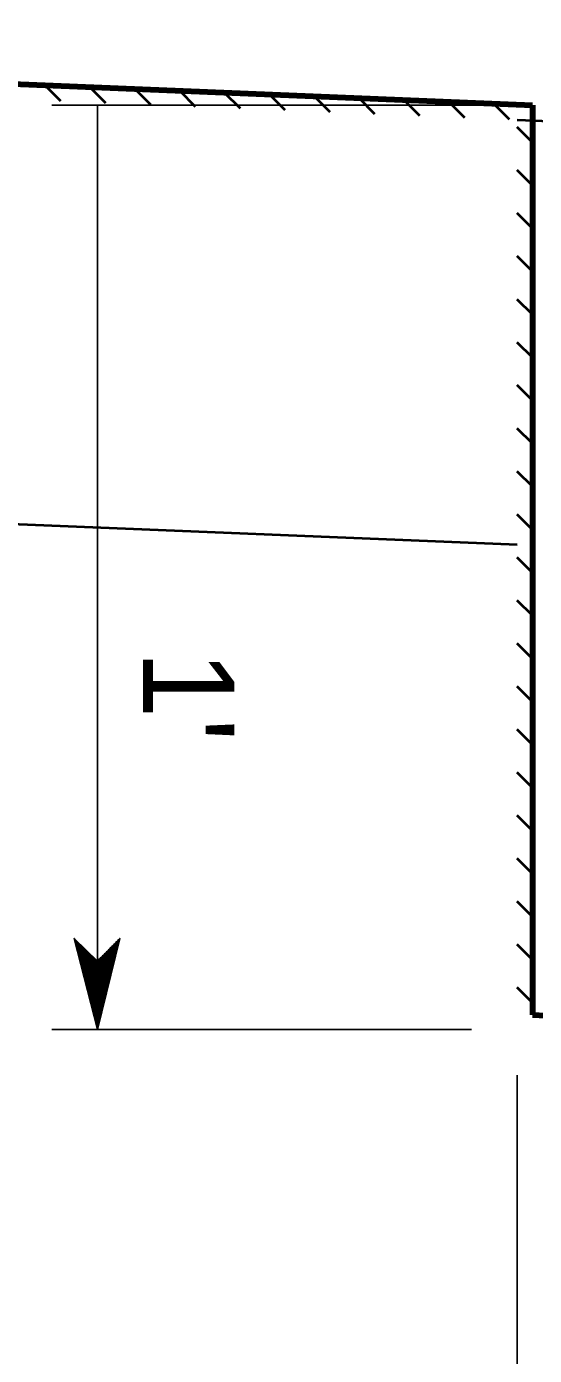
# Model space of a CAD drawing. Extents: x -48732 to -48696.6, y -117659.8 to -117637.8.
# Drawn here: x -48725.971 to -48725.536, y -117657.175 to -117656.038 of the extents above; entities that cross this region are included whole.
import ezdxf

# ---------------------------------------------------------------- set-up
doc = ezdxf.new("R2010")
doc.units = 0
doc.header["$LTSCALE"] = 0.048
doc.linetypes.add('DOTTED', pattern=[1.5, 0.3, -1.2])
doc.layers.add('11', color=7, linetype='Continuous', lineweight=25)
doc.layers.add('24', color=7, linetype='Continuous', lineweight=40)

msp = doc.modelspace()

# ---------------------------------------------------------------- linework, layer by layer
at = {"layer": '11'}
for p, q in [((-48725.57708, -117656.10492), (-48725.94942, -117656.10492)), ((-48725.91042, -117656.89617), (-48725.91042, -117656.10492)), ((-48725.92992, -117656.81833), (-48725.93008, -117656.81842)), ((-48725.92958, -117656.81858), (-48725.93, -117656.81892)), ((-48725.92925, -117656.81892), (-48725.92992, -117656.81942)), ((-48725.92892, -117656.81925), (-48725.92975, -117656.81983)), ((-48725.92858, -117656.81958), (-48725.92958, -117656.82025)), ((-48725.92825, -117656.81992), (-48725.92958, -117656.82075)), ((-48725.928, -117656.82025), (-48725.92942, -117656.82125)), ((-48725.92767, -117656.82058), (-48725.92925, -117656.82167)), ((-48725.92742, -117656.82092), (-48725.92925, -117656.82208)), ((-48725.92708, -117656.82125), (-48725.92908, -117656.82258)), ((-48725.92675, -117656.8215), (-48725.92892, -117656.82308)), ((-48725.92642, -117656.82175), (-48725.92883, -117656.8235)), ((-48725.92608, -117656.82208), (-48725.92875, -117656.82392)), ((-48725.92575, -117656.82242), (-48725.92858, -117656.82442)), ((-48725.92542, -117656.82275), (-48725.92842, -117656.82492)), ((-48725.92508, -117656.82308), (-48725.92842, -117656.82533)), ((-48725.92475, -117656.82342), (-48725.92825, -117656.82575)), ((-48725.92442, -117656.82375), (-48725.92808, -117656.82625)), ((-48725.92408, -117656.82408), (-48725.92808, -117656.82675)), ((-48725.92375, -117656.82442), (-48725.92792, -117656.82708)), ((-48725.9235, -117656.82467), (-48725.92775, -117656.82758)), ((-48725.92317, -117656.825), (-48725.92767, -117656.82808)), ((-48725.92292, -117656.82525), (-48725.92758, -117656.82858)), ((-48725.92258, -117656.82558), (-48725.92742, -117656.82892)), ((-48725.89292, -117656.82525), (-48725.90958, -117656.83658)), ((-48725.89275, -117656.82458), (-48725.90792, -117656.83492)), ((-48725.89258, -117656.82392), (-48725.90625, -117656.83325)), ((-48725.89242, -117656.82325), (-48725.90458, -117656.83158)), ((-48725.89225, -117656.82267), (-48725.90292, -117656.82992)), ((-48725.89208, -117656.822), (-48725.90125, -117656.82825)), ((-48725.89192, -117656.82142), (-48725.89967, -117656.82658)), ((-48725.89175, -117656.82075), (-48725.89808, -117656.82492)), ((-48725.89167, -117656.82008), (-48725.89642, -117656.82325)), ((-48725.8915, -117656.81942), (-48725.89475, -117656.82158)), ((-48725.89142, -117656.81875), (-48725.89308, -117656.81992)), ((-48725.89125, -117656.81808), (-48725.89142, -117656.81825)), ((-48725.92225, -117656.82592), (-48725.92725, -117656.82942)), ((-48725.92192, -117656.82625), (-48725.92725, -117656.82992)), ((-48725.92158, -117656.82658), (-48725.92708, -117656.83042)), ((-48725.92125, -117656.82692), (-48725.92692, -117656.83075)), ((-48725.92092, -117656.82725), (-48725.92692, -117656.83125)), ((-48725.92058, -117656.82758), (-48725.92675, -117656.83175)), ((-48725.92025, -117656.82792), (-48725.92658, -117656.83225)), ((-48725.91992, -117656.82817), (-48725.9265, -117656.83258)), ((-48725.91958, -117656.82842), (-48725.92642, -117656.83308)), ((-48725.91925, -117656.82875), (-48725.92625, -117656.83358)), ((-48725.919, -117656.82908), (-48725.92617, -117656.83408)), ((-48725.91867, -117656.82942), (-48725.92608, -117656.83442)), ((-48725.91842, -117656.82975), (-48725.92592, -117656.83492)), ((-48725.91808, -117656.83008), (-48725.92575, -117656.83542)), ((-48725.91775, -117656.83042), (-48725.92575, -117656.83583)), ((-48725.91742, -117656.83075), (-48725.92558, -117656.83625)), ((-48725.91708, -117656.83108), (-48725.92542, -117656.83675)), ((-48725.91675, -117656.83133), (-48725.92533, -117656.83725)), ((-48725.91642, -117656.83158), (-48725.92525, -117656.83767)), ((-48725.91608, -117656.83192), (-48725.92508, -117656.83808)), ((-48725.91575, -117656.83225), (-48725.925, -117656.83858)), ((-48725.91542, -117656.83258), (-48725.92492, -117656.83908)), ((-48725.91508, -117656.83292), (-48725.92475, -117656.8395)), ((-48725.91483, -117656.83325), (-48725.92458, -117656.83992)), ((-48725.9145, -117656.83358), (-48725.92458, -117656.84042)), ((-48725.91425, -117656.83392), (-48725.92442, -117656.84092)), ((-48725.91392, -117656.83425), (-48725.92425, -117656.84133)), ((-48725.91358, -117656.8345), (-48725.92425, -117656.84175)), ((-48725.91325, -117656.83483), (-48725.92408, -117656.84225)), ((-48725.91292, -117656.83508), (-48725.92392, -117656.84275)), ((-48725.91258, -117656.83542), (-48725.92383, -117656.84317)), ((-48725.91225, -117656.83575), (-48725.92375, -117656.84358)), ((-48725.91192, -117656.83608), (-48725.92358, -117656.84408)), ((-48725.91158, -117656.83642), (-48725.92342, -117656.84458)), ((-48725.91125, -117656.83675), (-48725.92342, -117656.845)), ((-48725.91092, -117656.83708), (-48725.92325, -117656.84542)), ((-48725.89308, -117656.82592), (-48725.92308, -117656.84642)), ((-48725.89325, -117656.82658), (-48725.92292, -117656.84675)), ((-48725.89342, -117656.82717), (-48725.92275, -117656.84725)), ((-48725.89358, -117656.82783), (-48725.92267, -117656.84775)), ((-48725.89375, -117656.82842), (-48725.92258, -117656.84825)), ((-48725.89392, -117656.82908), (-48725.92242, -117656.84858)), ((-48725.89408, -117656.82975), (-48725.92225, -117656.84908)), ((-48725.89425, -117656.83042), (-48725.92225, -117656.84958)), ((-48725.89442, -117656.83108), (-48725.92208, -117656.85008)), ((-48725.89458, -117656.83175), (-48725.92192, -117656.85042)), ((-48725.89467, -117656.83233), (-48725.92192, -117656.85092)), ((-48725.89483, -117656.83292), (-48725.92175, -117656.85142)), ((-48725.895, -117656.83358), (-48725.92158, -117656.85192)), ((-48725.89508, -117656.83425), (-48725.9215, -117656.85225)), ((-48725.89525, -117656.83492), (-48725.92142, -117656.85275)), ((-48725.89542, -117656.83558), (-48725.92125, -117656.85325)), ((-48725.89558, -117656.83625), (-48725.92117, -117656.85367)), ((-48725.89575, -117656.83692), (-48725.92108, -117656.85408)), ((-48725.91058, -117656.83742), (-48725.92308, -117656.84592)), ((-48725.89592, -117656.8375), (-48725.92092, -117656.85458)), ((-48725.89608, -117656.83808), (-48725.92075, -117656.85508)), ((-48725.89625, -117656.83875), (-48725.92075, -117656.8555)), ((-48725.89642, -117656.83942), (-48725.92058, -117656.85592)), ((-48725.89658, -117656.84008), (-48725.92042, -117656.85642)), ((-48725.89675, -117656.84075), (-48725.92033, -117656.85692)), ((-48725.89692, -117656.84142), (-48725.92025, -117656.85733)), ((-48725.89708, -117656.84208), (-48725.92008, -117656.85775)), ((-48725.89725, -117656.84267), (-48725.92, -117656.85825)), ((-48725.89742, -117656.84325), (-48725.91992, -117656.85875)), ((-48725.89758, -117656.84392), (-48725.91975, -117656.85917)), ((-48725.89775, -117656.84458), (-48725.91958, -117656.85958)), ((-48725.89792, -117656.84525), (-48725.91958, -117656.86008)), ((-48725.898, -117656.84592), (-48725.91942, -117656.86058)), ((-48725.89817, -117656.84658), (-48725.91925, -117656.861)), ((-48725.89825, -117656.84725), (-48725.91925, -117656.86142)), ((-48725.89842, -117656.84783), (-48725.91908, -117656.86192)), ((-48725.89858, -117656.84842), (-48725.91892, -117656.86242)), ((-48725.89875, -117656.84908), (-48725.91883, -117656.86283)), ((-48725.89892, -117656.84975), (-48725.91875, -117656.86325)), ((-48725.89908, -117656.85042), (-48725.91858, -117656.86375)), ((-48725.89925, -117656.85108), (-48725.91842, -117656.86425)), ((-48725.89942, -117656.85175), (-48725.91842, -117656.86458)), ((-48725.89958, -117656.85233), (-48725.91825, -117656.86508)), ((-48725.89975, -117656.853), (-48725.91808, -117656.86558)), ((-48725.89992, -117656.85358), (-48725.91808, -117656.86608)), ((-48725.90008, -117656.85425), (-48725.91792, -117656.86642)), ((-48725.90025, -117656.85492), (-48725.91775, -117656.86692)), ((-48725.90042, -117656.85558), (-48725.91767, -117656.86742)), ((-48725.90058, -117656.85625), (-48725.91758, -117656.86792)), ((-48725.90075, -117656.85692), (-48725.91742, -117656.86825)), ((-48725.90092, -117656.8575), (-48725.91725, -117656.86875)), ((-48725.90108, -117656.85808), (-48725.91725, -117656.86925)), ((-48725.90117, -117656.85875), (-48725.91708, -117656.86975)), ((-48725.90133, -117656.85942), (-48725.91692, -117656.87008)), ((-48725.9015, -117656.86008), (-48725.91692, -117656.87058)), ((-48725.90158, -117656.86075), (-48725.91675, -117656.87108)), ((-48725.90175, -117656.86142), (-48725.91658, -117656.8715)), ((-48725.90192, -117656.86208), (-48725.9165, -117656.87192)), ((-48725.90208, -117656.86267), (-48725.91642, -117656.87242)), ((-48725.90225, -117656.86325), (-48725.91625, -117656.87292)), ((-48725.90242, -117656.86392), (-48725.91617, -117656.87333)), ((-48725.90258, -117656.86458), (-48725.91608, -117656.87375)), ((-48725.90275, -117656.86525), (-48725.91592, -117656.87425)), ((-48725.90292, -117656.86592), (-48725.91575, -117656.87475)), ((-48725.90308, -117656.86658), (-48725.91575, -117656.87517)), ((-48725.90325, -117656.86725), (-48725.91558, -117656.87558)), ((-48725.90342, -117656.86783), (-48725.91542, -117656.87608)), ((-48725.90358, -117656.86842), (-48725.91533, -117656.87658)), ((-48725.90375, -117656.86908), (-48725.91525, -117656.877)), ((-48725.90392, -117656.86975), (-48725.91508, -117656.87742)), ((-48725.90408, -117656.87042), (-48725.915, -117656.87792)), ((-48725.90425, -117656.87108), (-48725.91492, -117656.87842)), ((-48725.90442, -117656.87175), (-48725.91475, -117656.87883)), ((-48725.9045, -117656.87242), (-48725.91458, -117656.87925)), ((-48725.90467, -117656.873), (-48725.91458, -117656.87975)), ((-48725.90483, -117656.87358), (-48725.91442, -117656.88025)), ((-48725.90492, -117656.87425), (-48725.91425, -117656.88067)), ((-48725.90508, -117656.87492), (-48725.91425, -117656.88108)), ((-48725.90525, -117656.87558), (-48725.91408, -117656.88158)), ((-48725.90542, -117656.87625), (-48725.91392, -117656.88208)), ((-48725.90558, -117656.87692), (-48725.91383, -117656.8825)), ((-48725.90575, -117656.87758), (-48725.91375, -117656.88292)), ((-48725.90592, -117656.87817), (-48725.91358, -117656.88342)), ((-48725.90608, -117656.87875), (-48725.91342, -117656.88392)), ((-48725.90625, -117656.87942), (-48725.91342, -117656.88425)), ((-48725.90642, -117656.88008), (-48725.91325, -117656.88475)), ((-48725.90658, -117656.88075), (-48725.91308, -117656.88525)), ((-48725.90675, -117656.88142), (-48725.91308, -117656.88575)), ((-48725.90692, -117656.88208), (-48725.91292, -117656.88608)), ((-48725.90708, -117656.88267), (-48725.91275, -117656.88658)), ((-48725.90725, -117656.88333), (-48725.91267, -117656.88708)), ((-48725.90742, -117656.88392), (-48725.91258, -117656.88758)), ((-48725.90758, -117656.88458), (-48725.91242, -117656.88792)), ((-48725.90775, -117656.88525), (-48725.91225, -117656.88842)), ((-48725.90783, -117656.88592), (-48725.91225, -117656.88892)), ((-48725.908, -117656.88658), (-48725.91208, -117656.88942)), ((-48725.90808, -117656.88725), (-48725.91192, -117656.88975)), ((-48725.90825, -117656.88783), (-48725.91192, -117656.89025)), ((-48725.90842, -117656.88842), (-48725.91175, -117656.89075)), ((-48725.90858, -117656.88908), (-48725.91158, -117656.89117)), ((-48725.90875, -117656.88975), (-48725.9115, -117656.89158)), ((-48725.90892, -117656.89042), (-48725.91142, -117656.89208)), ((-48725.90908, -117656.89108), (-48725.91125, -117656.89258)), ((-48725.90925, -117656.89175), (-48725.91117, -117656.893)), ((-48725.90942, -117656.89242), (-48725.91108, -117656.89342)), ((-48725.90958, -117656.893), (-48725.91092, -117656.89392)), ((-48725.90975, -117656.89358), (-48725.91075, -117656.89442)), ((-48725.59008, -117656.89617), (-48725.94942, -117656.89617)), ((-48725.90992, -117656.89425), (-48725.91075, -117656.89483)), ((-48725.91008, -117656.89492), (-48725.91058, -117656.89525)), ((-48725.91025, -117656.89558), (-48725.91042, -117656.89575)), ((-48725.551, -117656.93525), (-48725.551, -117657.77692))]:
    msp.add_line(p, q, dxfattribs=at)
msp.add_lwpolyline([(-48725.91042, -117656.89617), (-48725.89117, -117656.81808), (-48725.91042, -117656.83758), (-48725.93025, -117656.81808)], close=True, dxfattribs=at)
at = {"layer": '24', "lineweight": 106}
for p, q in [((-48727.18058, -117656.03758), (-48725.53792, -117656.10492)), ((-48725.53792, -117656.10492), (-48725.53792, -117656.88367)), ((-48725.53792, -117656.88367), (-48724.97125, -117656.90875))]:
    msp.add_line(p, q, dxfattribs=at)
at = {"layer": '24'}
for p, q in [((-48725.94158, -117656.10142), (-48725.95508, -117656.08792)), ((-48725.90308, -117656.10308), (-48725.91675, -117656.08942)), ((-48725.86475, -117656.10458), (-48725.87833, -117656.091)), ((-48725.82642, -117656.10617), (-48725.83992, -117656.09258)), ((-48725.78792, -117656.10775), (-48725.80158, -117656.09417)), ((-48725.74958, -117656.10925), (-48725.76308, -117656.09575)), ((-48725.71108, -117656.11092), (-48725.72475, -117656.09725)), ((-48725.67275, -117656.11242), (-48725.68625, -117656.09892)), ((-48725.63433, -117656.11408), (-48725.64792, -117656.10042)), ((-48725.59592, -117656.11558), (-48725.6095, -117656.10208)), ((-48725.55758, -117656.11725), (-48725.57108, -117656.10358)), ((-48725.53792, -117656.13675), (-48725.551, -117656.12375)), ((-48725.53792, -117656.17358), (-48725.551, -117656.16058)), ((-48725.53792, -117656.21042), (-48725.551, -117656.19742)), ((-48725.53792, -117656.24725), (-48725.551, -117656.23425)), ((-48725.53792, -117656.28408), (-48725.551, -117656.27108)), ((-48725.53792, -117656.32092), (-48725.551, -117656.30792)), ((-48725.53792, -117656.35775), (-48725.551, -117656.34467)), ((-48725.53792, -117656.39458), (-48725.551, -117656.3815)), ((-48727.18275, -117656.41392), (-48725.551, -117656.48092)), ((-48725.53792, -117656.43142), (-48725.551, -117656.41833)), ((-48725.53792, -117656.46825), (-48725.551, -117656.45517)), ((-48725.53792, -117656.50508), (-48725.551, -117656.492)), ((-48725.53792, -117656.54183), (-48725.551, -117656.52875)), ((-48725.53792, -117656.57867), (-48725.551, -117656.56558)), ((-48725.53792, -117656.6155), (-48725.551, -117656.60242)), ((-48725.53792, -117656.65233), (-48725.551, -117656.63925)), ((-48725.53792, -117656.68917), (-48725.551, -117656.67608)), ((-48725.53792, -117656.72592), (-48725.551, -117656.71292)), ((-48725.53792, -117656.76275), (-48725.551, -117656.74975)), ((-48725.53792, -117656.79958), (-48725.551, -117656.78658)), ((-48725.53792, -117656.83642), (-48725.551, -117656.82342)), ((-48725.53792, -117656.87325), (-48725.551, -117656.86025))]:
    msp.add_line(p, q, dxfattribs=at)
at = {"layer": '24', "linetype": 'DOTTED'}
msp.add_line((-48725.551, -117656.11742), (-48723.96792, -117656.18242), dxfattribs=at)

# ---------------------------------------------------------------- texts
at = {"layer": '11'}
msp.add_text("  1'", height=0.07812, rotation=270, dxfattribs=at).set_placement((-48725.87125, -117656.5135))

doc.saveas('drawing.dxf')
